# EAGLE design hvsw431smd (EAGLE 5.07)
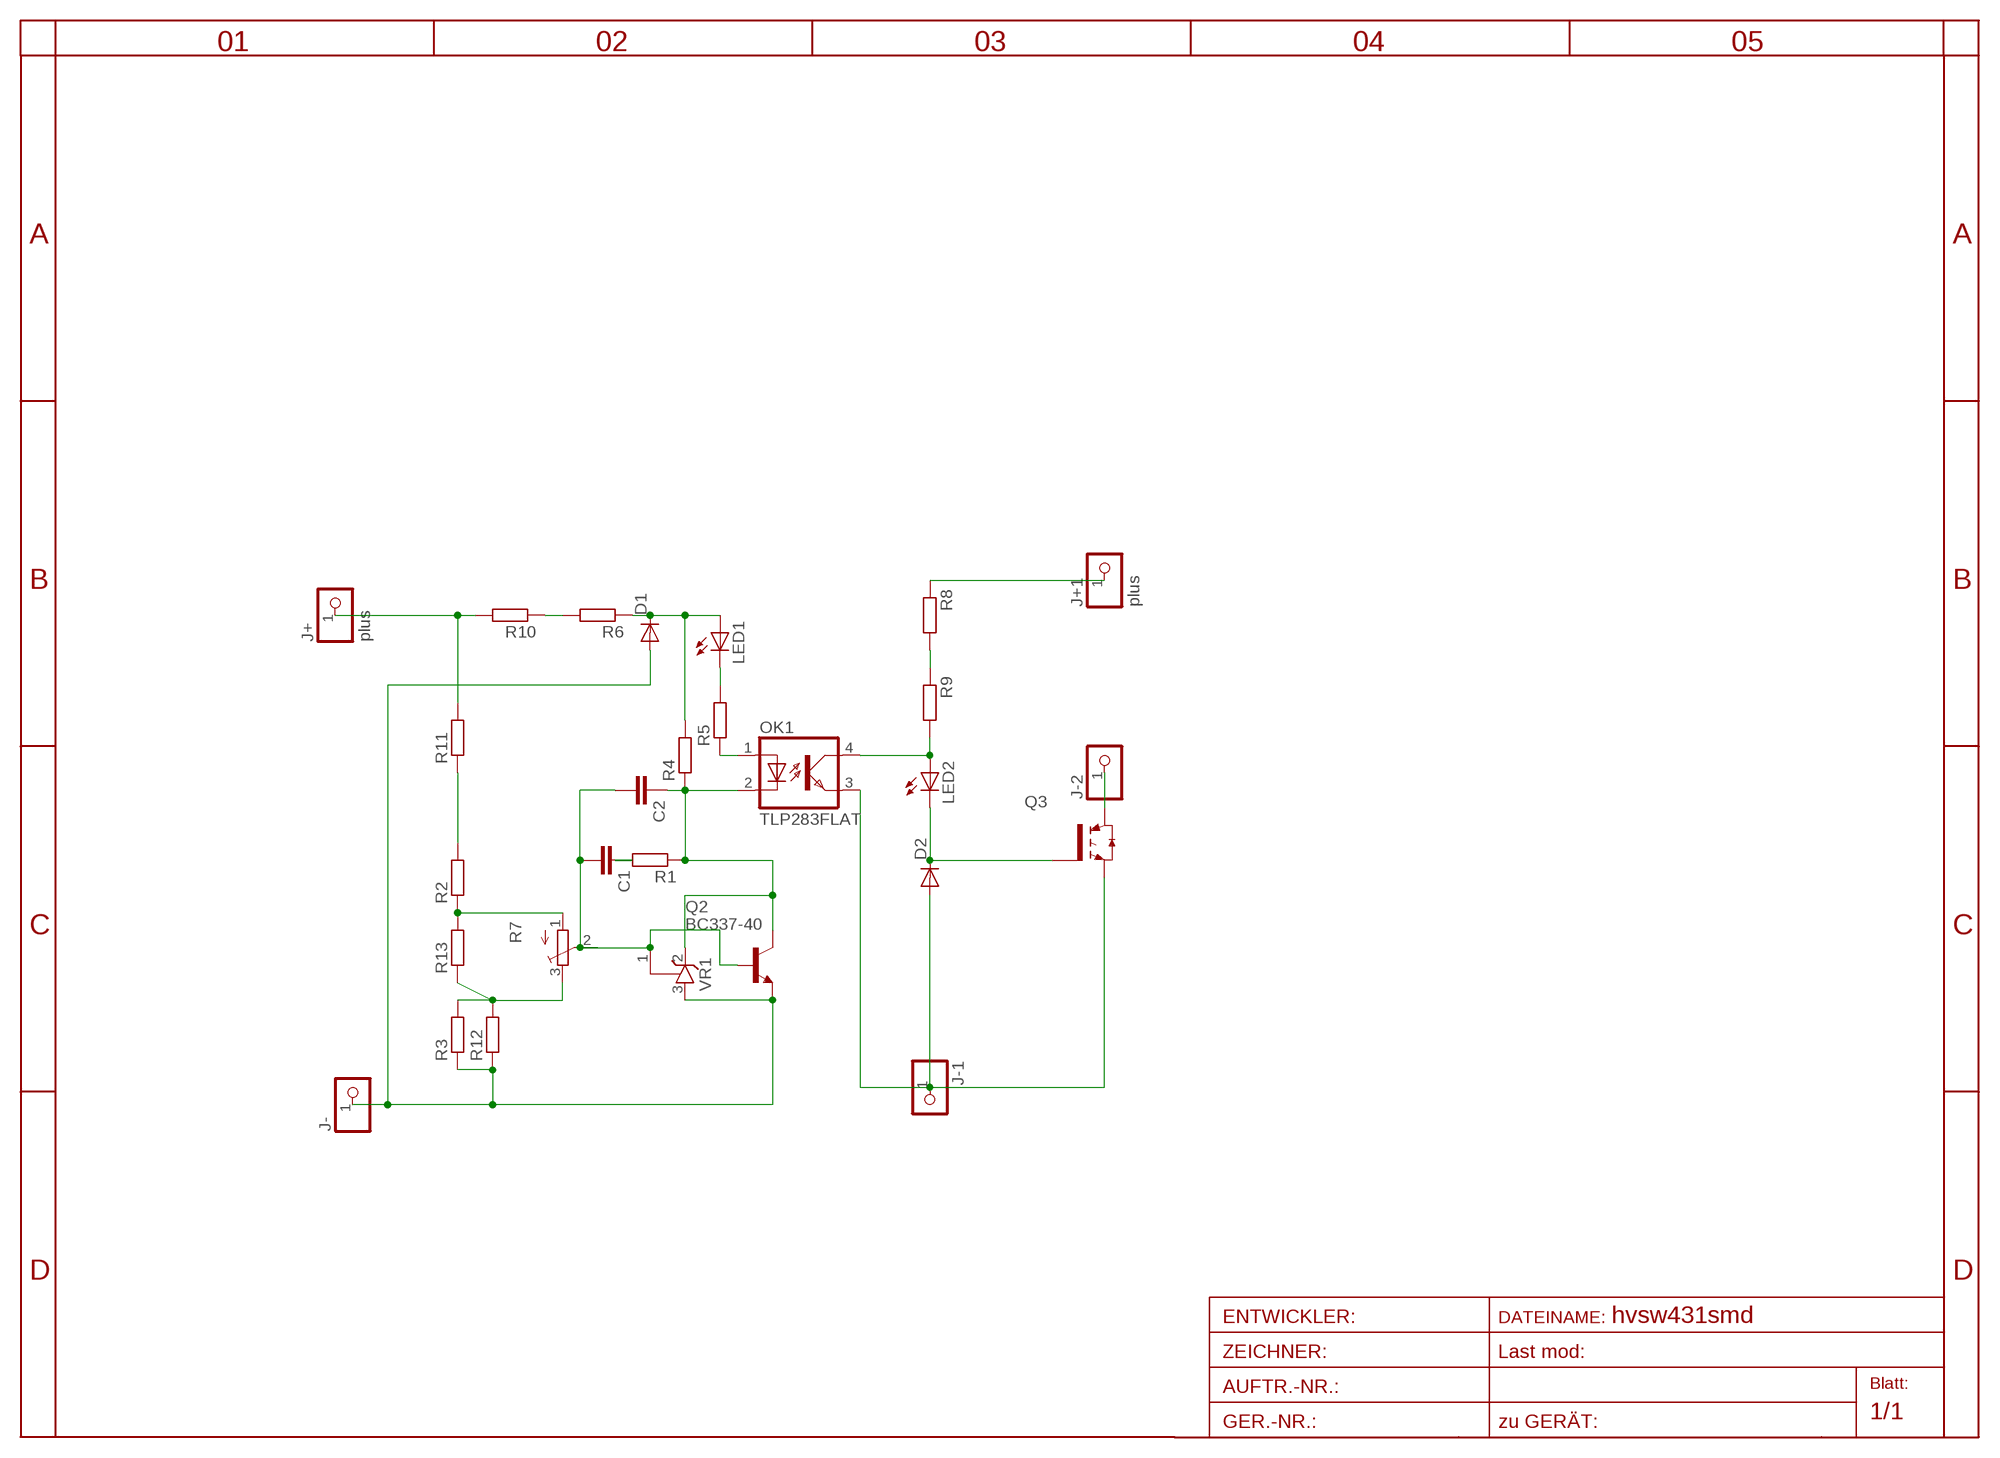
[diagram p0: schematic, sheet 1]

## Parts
C1  C-EUC0805  [C0805]
C2  C-EUC0805  [C0805]
D1  DIODE-MINIMELF  [MINIMELF]
D2  DIODE-MINIMELF  [MINIMELF]
J+  plus  PINHD-1X11X0.4  [1X01]
J+1  plus  PINHD-1X11X0.4  [1X01]
J-  PINHD-1X11X0.4  [1X01]
J-1  PINHD-1X12MM2  [1X2MM2]
J-2  PINHD-1X11MM6  [1X1MM8]
LED1  LEDCHIPLED_1206  [CHIPLED_1206]
LED2  LEDCHIPLED_1206  [CHIPLED_1206]
OK1  TLP283FLAT  [FLAT-4]
Q2  BC337-40  [TO92]
Q3  IRG4BC15UD-S  [D2PACK]
R1  R-EU_R0805  [R0805]
R2  R-EU_R1206  [R1206]
R3  R-EU_R0805  [R0805]
R4  R-EU_R0805  [R0805]
R5  R-EU_R0805  [R0805]
R6  R-EU_R1206  [R1206]
R7  TRIM_EU-3223G  [3223G]
R8  R-EU_R1206  [R1206]
R9  R-EU_R1206  [R1206]
R10  R-EU_R1206  [R1206]
R11  R-EU_R1206  [R1206]
R12  R-EU_R0805  [R0805]
R13  R-EU_R0805  [R0805]
VR1  TL431CLPSOT23  [SOT23]

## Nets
A: R3.2 R7.3(E) R12.2 R13.1
E: R2.1 R7.1(A) R13.2
GND-: D1.A J-.1 Q2.1(E) R3.1 R12.1 VR1.3(A)
LEDA: D1.C LED1.A R4.2 R6.1
N$3: C1.1 R1.2
N$8: J+1.1 R8.1
N$11: D2.C LED2.C Q3.1(G)
N$12: R8.2 R9.1
N$13: J-2.1 Q3.2(C)
N$15: R2.2 R11.1
N$16: R6.2 R10.1
N$17: LED2.A OK1.4(COL) R9.2
N$18: LED1.C R5.2
OPTOA: OK1.1(A) R5.1
OPTOK: C2.1 OK1.2(C) Q2.3(C) R1.1 R4.1 VR1.2(C)
PLUS: J+.1 R10.2 R11.2
S: C1.2 C2.2 Q2.2(B) R7.2(S) VR1.1(R)
WE: D2.A J-1.1 OK1.3(EMIT) Q3.3(E)

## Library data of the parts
C1 C2 = rcl:C-EU: CAPACITOR, European symbol
D1 D2 = diode:DIODE-: DIODE
J+ J+1 J- J-1 J-2 = pinhead:PINHD-1X1: PIN HEADER
LED1 LED2 = led:LED: LED
OK1 = optocoupler:TLP283: TOSHIBA PHOTOCOUPLER GaAs IRED & PHOTO-TRANSISTOR Source: http://www.semicon.toshiba.co.jp/td/en/Opto/Photocoupler/en_20050928_TLP283_datasheet.pdf
Q2 = transistor-npn:BC337*: NPN Transistor
Q3 = transistor-power:IRG4BC15UD-: INSULATED GATE BIPOLAR TRANSISTOR WITH ULTRAFAST SOFT RECOVERY DIODE
R1-R6 R8-R13 = rcl:R-EU_: RESISTOR, European symbol
R7 = pot:TRIM_EU-: POTENTIOMETER
VR1 = v-reg:TL431CLP: VOLTAGE REGULATOR

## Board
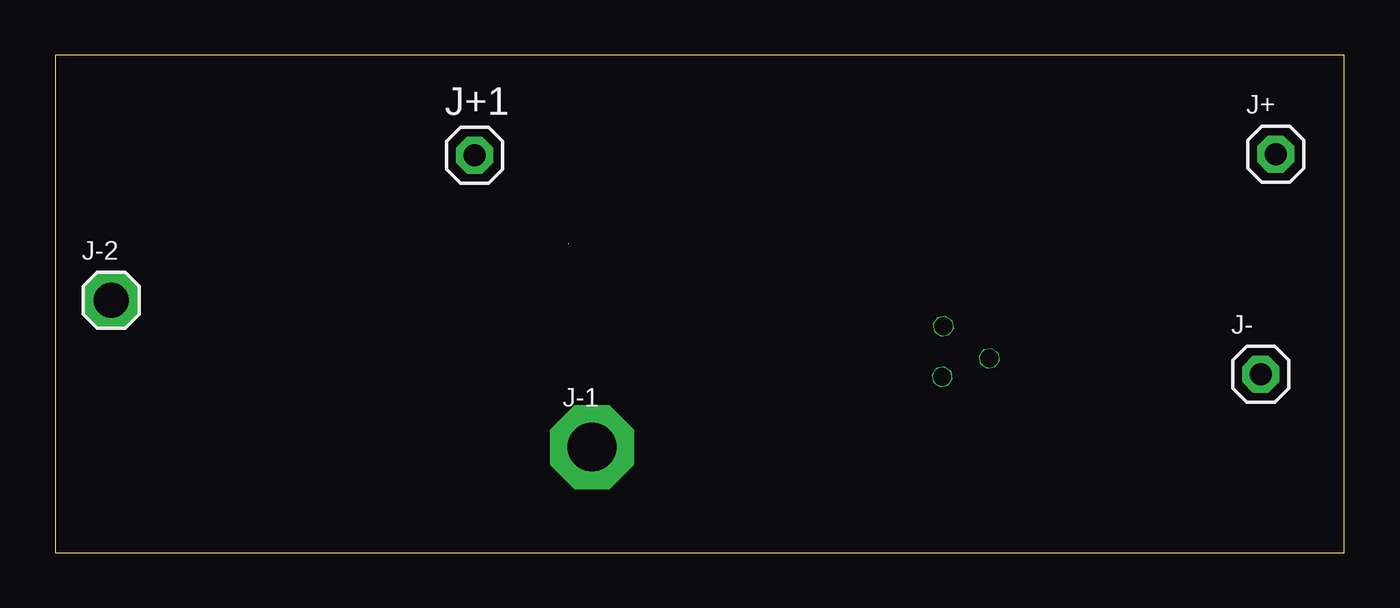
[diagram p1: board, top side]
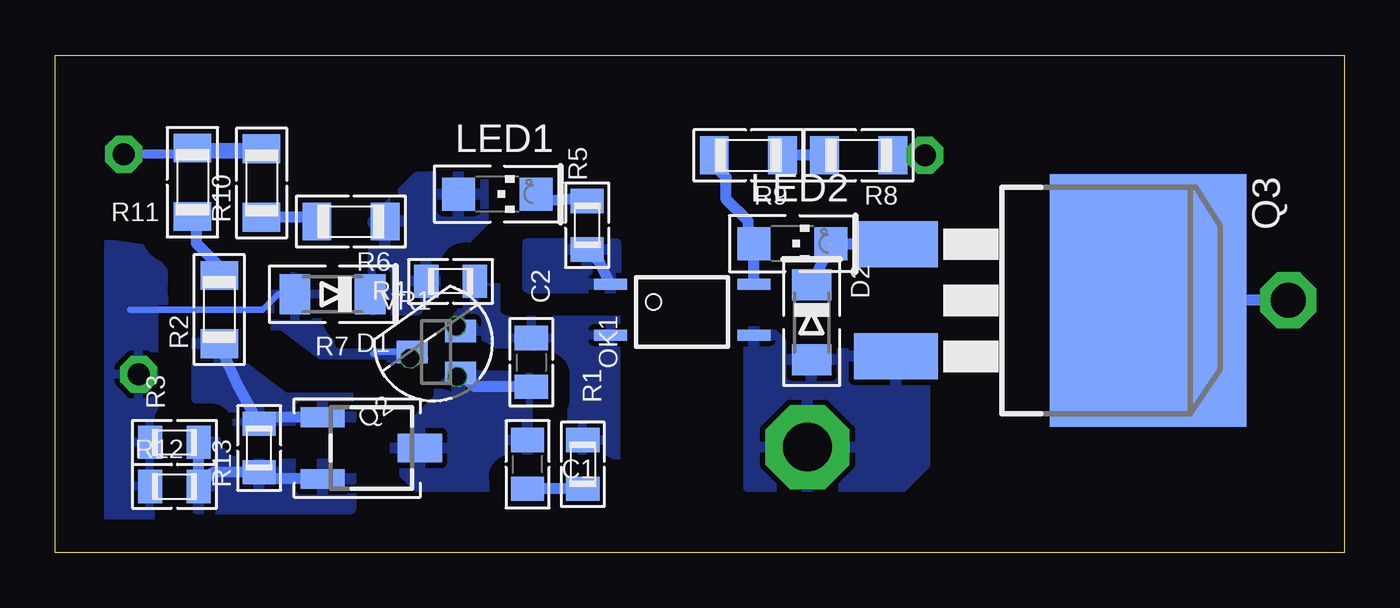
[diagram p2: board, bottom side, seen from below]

Size 58.4 x 22.53 mm. Coordinates in mm from the lower left corner, seen from the top.
Outline: 0,0 58.4,0 58.4,22.53 0,22.53 0,0
Copper layers (1*16): Top 0.035mm / dielectric 1.5mm / Bottom 0.035mm
Design rules "default": minimum track width 10mil, minimum drill 20mil, track to track 8mil, track to pad 8mil, pad to pad 8mil, via to via 8mil, smd to smd 8mil, copper to edge 40mil, drill to drill 8mil, minimum pad ring 1mil, minimum via ring 8mil, stop-mask expansion 4mil, vias tented up to drill 0mil, thermal gap 10mil

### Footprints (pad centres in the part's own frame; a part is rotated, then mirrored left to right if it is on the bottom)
C0805 = smd 1.1 x 1.5: 1 -1.1,0; 2 1.1,0
MINIMELF = smd 1.4 x 1.8: A 1.7,0; C -1.7,0
1X01 = drill 1 pad 1.676 octagon: 1 0,0
1X2MM2 = drill 2.2 pad 3.81 octagon: 1 0,0
1X1MM8 = drill 1.6 pad 2.54 octagon: 1 0,0
CHIPLED_1206 = smd 1.5 x 1.5: A 0,-1.75; C 0,1.75
FLAT-4 = smd 1.5 x 0.5: 1 -3.25,1.15; 2 -3.25,-1.15; 3 3.25,-1.15; 4 3.25,1.15
TO92 = drill 0.813 octagon: 1 1.27,0; 2 0,1.905; 3 -1.27,0
D2PACK = smd 2.083 x 3.81: 1 -2.54,-8.89; 3 2.54,-8.89 | smd 11.43 x 8.89: 2 0,2.54
R0805 = smd 1.1 x 1.5: 1 -1.1,0; 2 1.1,0
R1206 = smd 1.3 x 1.7: 1 -1.55,0; 2 1.55,0
3223G = smd 2 x 0.9: 1 -2.2,1.4; 3 -2.2,-1.4 | smd 2 x 1.3: 2 2.2,0
SOT23 = smd 1 x 1.4: 1 -0.95,-1.1; 2 0.95,-1.1; 3 0,1.1

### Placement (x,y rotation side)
C1  37,4 90 bottom
C2  36.83,8.62 270 bottom
D1  45.84,11.71 180 bottom
D2  24.13,10.43 270 bottom
J+  55.29,18.05 0 top
J+1  19,18 0 top
J-  54.61,8.08 0 top
J-1  24.32,4.78 0 top
J-2  2.54,11.43 0 top
LED1  38.37,16.24 270 bottom
LED2  25,14 270 bottom
OK1  30,11 0 bottom
Q2  41.27,9.53 215 bottom
Q3  11.43,11.43 270 bottom
R1  34.5,4 270 bottom
R2  50.97,11.01 90 bottom
R3  53,5 0 bottom
R4  40.49,12.29 180 bottom
R5  34.3,14.83 90 bottom
R6  45,15 180 bottom
R7  44.08,4.74 0 bottom
R8  22,18 180 bottom
R9  27,18 180 bottom
R10  49.05,16.74 90 bottom
R11  52.18,16.78 90 bottom
R12  53,3 0 bottom
R13  49.16,4.74 90 bottom
VR1  41.14,9.09 90 bottom

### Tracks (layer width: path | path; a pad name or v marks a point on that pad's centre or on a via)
A
  Bottom 0.5: R7.3 48.86,3.34 R13.1 51.26,3.64 R12.2 R3.2
  pour Bottom (isolate 1): 45,4 50,4 51,5 52,5 52,2 45,2
E
  Bottom 0.5: R7.1 48.86,6.14 R13.2 50.16,7.65 R2.1
  pour Bottom (isolate 1): 48,7 52,10 52,7 51,6 45,6 45,7
GND-
  Bottom 0.3: D1.A 48.3,11.71 49,11 55,11 | VR1.3 43.91,9.09 44,9
  Bottom 0.5: Q2.1 41.74,8.8 VR1.3
  pour Bottom (isolate 1.5, rank 3): 42,12 56,14 56,1 51,2 42,7
LEDA
  pour Bottom (isolate 1): 39,17 42,17 44,15 44,11 42,11 41,12 41,13 39,15
N$3
  Bottom 0.5: R1.2 C1.1
N$8
  Bottom 0.5: J+1.1 R8.1
N$11  (1 unrouted)
  Bottom 0.5: Q3.1 23.29,13.97 D2.C
N$12
  Bottom 0.5: R8.2 R9.1
N$13
  Bottom 0.5: J-2.1 Q3.2
N$15
  Bottom 0.5: R2.2 50.97,12.97 52,14 52,15.05 R11.1
N$16
  Bottom 0.5: R10.1 46.74,15.19 R6.2
N$17
  Bottom 0.5: R9.2 28.55,17.55 28,17 28,16 27,15 27,14.25 LED2.A OK1.4
N$18
  Bottom 0.5: R5.2 34.93,16.07 35,16 37,15.86 LED1.C
OPTOA
  Bottom 0.5: OK1.1 33.73,13.15 R5.1
  pour Bottom (isolate 1): 33,14 37,14 37,12 33,12
OPTOK
  Bottom 0.5: Q2.3 40.23,10.23 VR1.2
  pour Bottom (isolate 1, rank 5): 33,12 41,12 41,10 40,9 36,9 35,8 35,4 33,2
PLUS
  Bottom 0.406: J+.1 49.05,18.05 R10.2
  Bottom 0.5: R10.2 52.18,18.29 R11.2
S
  Bottom 0.5: C2.2 39.42,7.52 VR1.1 40.18,8 Q2.2
  pour Bottom (isolate 1, rank 2): 37,8 41,8 41,7 43,5 43,4 42,3 38,3 37,4
WE
  pour Bottom (isolate 1): 19,9 25,9 26,10 27,10 27,3 20,3 19,4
